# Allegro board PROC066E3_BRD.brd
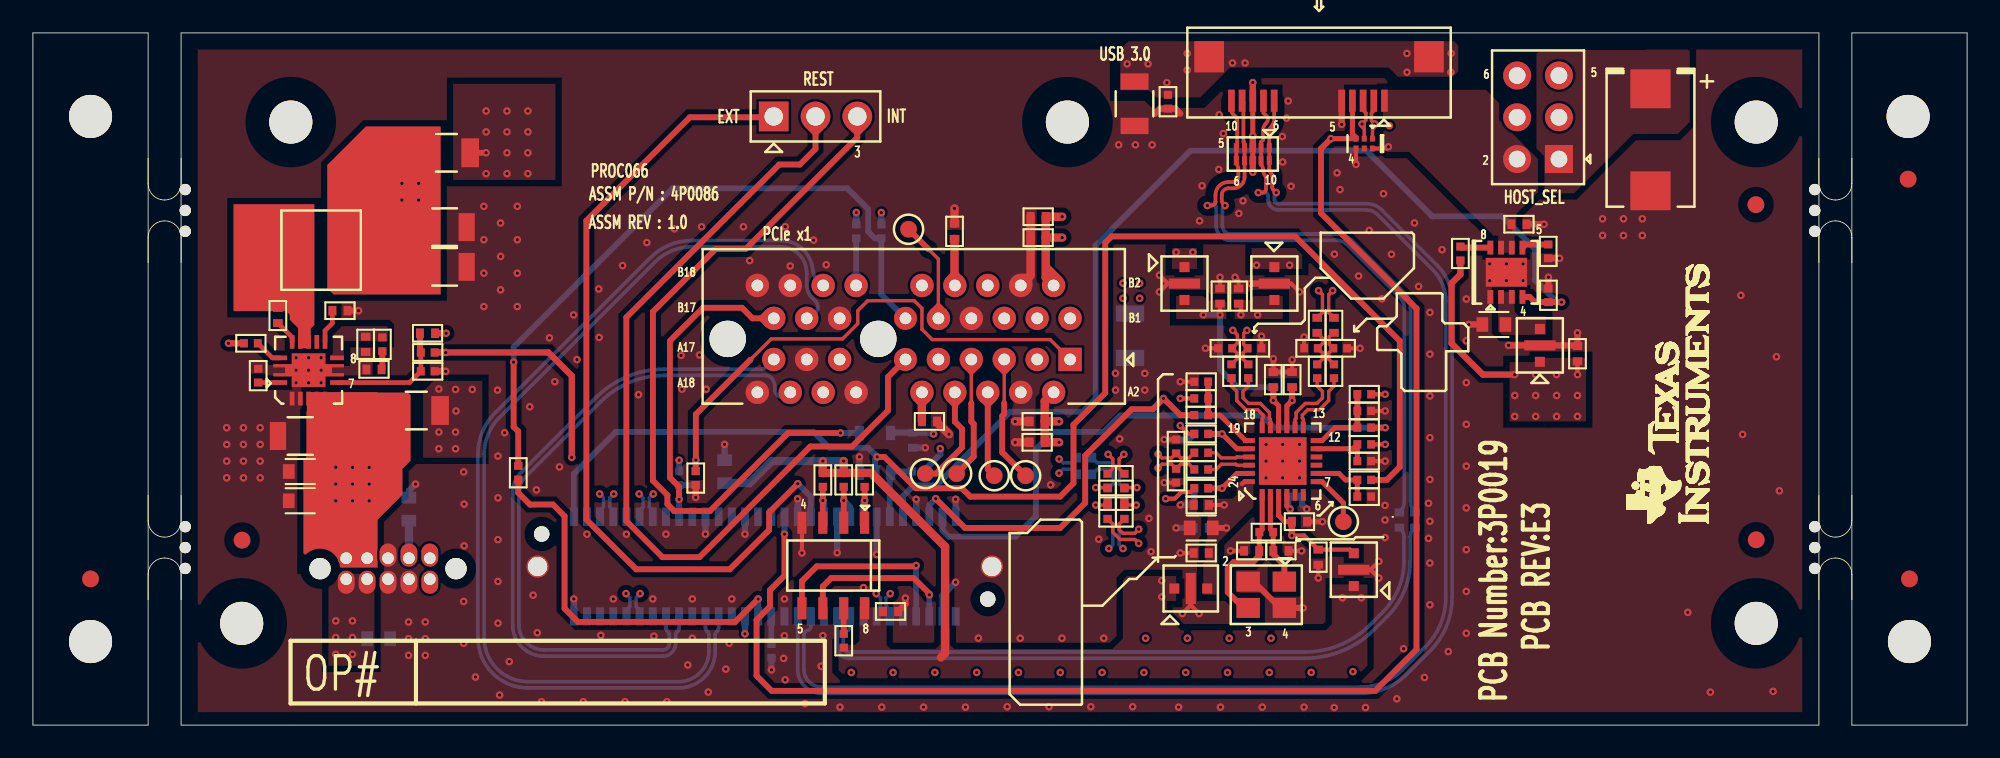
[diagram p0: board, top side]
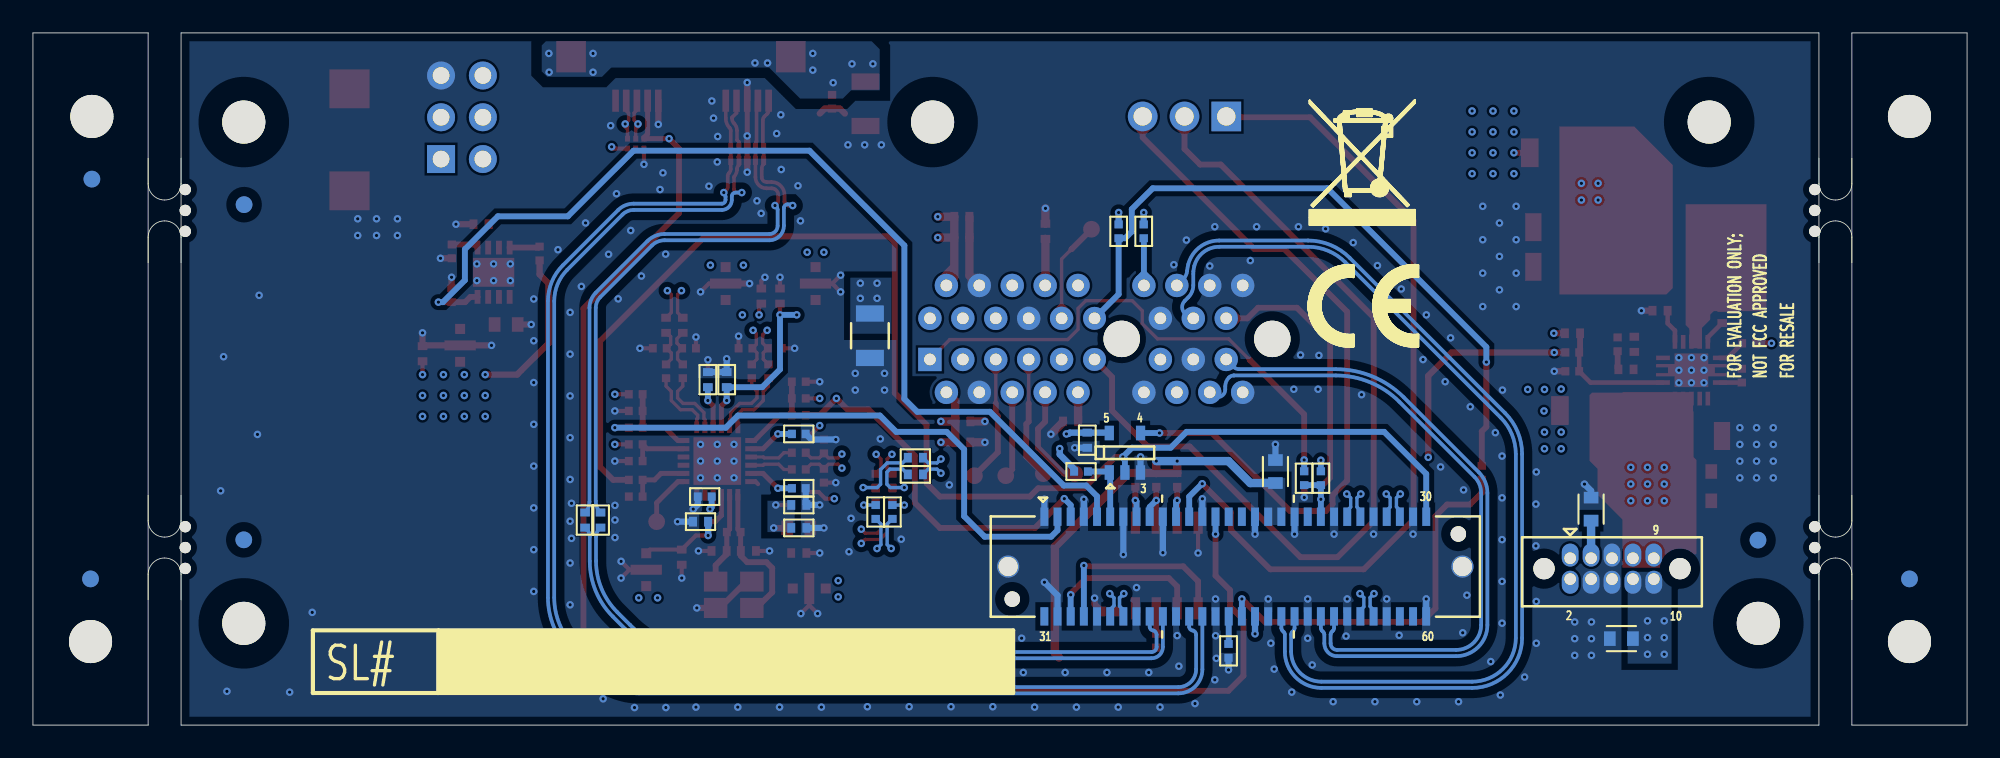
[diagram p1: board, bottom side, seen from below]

Outline 117.5 x 42.09 mm; copper layers: TOP, L02_GND1, L03_PWR, L04_SIG1, L05_GND2, BOTTOM. Coordinates in mm from the lower left corner of the outline.
Outline path: 0,42.09 0,0 7,0 7,42.09 0,42.09 ; 9,42.09 9,0 108.5,0 108.5,42.09 9,42.09 ; 110.5,42.09 110.5,0 117.5,0 117.5,42.09 110.5,42.09

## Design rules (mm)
net group 2_REFCLK_OUT1N: nets 2_REFCLK_OUT1N N17071009
net group 2_REFCLK_OUT1P: nets 2_REFCLK_OUT1P N17070998
net group DIFF_2_CLKGEN_REFCLK1: nets 2_CLKGEN_REFCLK1N 2_CLKGEN_REFCLK1P
net group DIFF_2_CLKGEN_REFCLK2: nets 2_CLKGEN_REFCLK2N 2_CLKGEN_REFCLK2P
net group DIFF_2_PCIE_REFCLK: nets 2_PCIE_REFCLK_N 2_PCIE_REFCLK_P
net group DIFF_2_REFCLK_IN1: nets 2_REFCLK_IN1N 2_REFCLK_IN1P
net group DIFF_2_REFCLK_OUT0: nets 2_REFCLK_OUT0N 2_REFCLK_OUT0P
net group DIFF_2_USB_D: nets 2_USB_DM 2_USB_DP
net group DIFF_CDCI2_Y1: nets CDCI2_Y1N CDCI2_Y1P
net group DIFF_CDCI2_Y2: nets CDCI2_Y2N CDCI2_Y2P
net group DIFF_CDCI2_Y3: nets CDCI2_Y3N CDCI2_Y3P
net group DIFF_CDCI2_Y3_R: nets N16935843 N16935846
net group 2_USB3_RXN: nets 2_USB3_RXN
net group 2_USB3_RXP: nets 2_USB3_RXP

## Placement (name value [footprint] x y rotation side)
C50  1000pF  [CAP1206]  66.92 37.78 270 top
C51  150uF_10V  [CAPT7343D_3-25]  98.27 35.59 270 top
C52  0.1uF  [CAP0402_0-75]  90.28 30.45 0 top
C53  0.01uF  [CAP0402]  61.07 30.91 180 top
C54  47uF  [CAP1206_2]  25 30.28 0 top
C55  0.1uF  [CAP0402_0-75]  55.99 30.02 90 top
C56  0.1uF  [CAP0402_0-75]  61.07 29.64 180 top
C57  10uF  [CAP0603_1]  88.76 24.36 180 top
C58  47uF  [CAP1206_2]  25 27.86 0 top
C59  0.1uF  [CAP0402_0-75]  93.84 22.58 90 top
C60  4.7uF  [CAP0402_0-75]  72.12 26.09 90 top
C61  4.7uF  [CAP0402_0-75]  73.25 26.09 90 top
C62  0.01uF  [CAP0402]  18.65 25.2 0 top
C63  0.1uF  [CAP0402_0-75]  14.88 24.9 270 top
C64  0.1uF  [CAP0402_0-75]  78.02 24.31 270 top
C65  0.1uF  [CAP0402_0-75]  79.04 24.31 270 top
C66  510pF  [CAP0402]  23.97 23.83 180 top
C67  91pF  [CAP0402]  20.21 23.15 270 top
C68  1500pF  [CAP0402]  20.72 21.63 180 top
C69  0.1uF  [CAP0402_0-75]  75.36 21.01 270 top
C70  0.1uF  [CAP0402_0-75]  76.5 21.01 270 top
C71  0.01uF  [CAP0402]  54.47 18.47 0 top
C72  0.1uF  [CAP0402_0-75]  61.01 18.47 180 top
C73  4.7uF  [CAP1206]  16.24 17.58 180 top
C74  0.01uF  [CAP0402]  61.01 17.2 180 top
C75  10uF  [CAP0603_1]  16.24 15.42 180 top
C76  10uF  [CAP0603_1]  16.24 13.64 180 top
C77  0.1uF  [CAP0402_0-75]  70.98 13.39 0 top
C78  0.1uF  [CAP0402_0-75]  76.94 12.37 180 top
C79  10uF  [CAP0603_1]  70.98 11.99 180 top
C80  27pF  [CAP0402]  74.04 10.59 0 top
C81  27pF  [CAP0402]  75.82 10.59 180 top
C82  4.7uF  [CAP0402_0-75]  70.98 10.46 180 top
C83  0.47uF  [CAP0402_0-75]  78.09 10.21 270 top
C84  0.1uF  [CAP0402_0-75]  52.1 6.91 0 top
C197  47uF  [CAP1206_2]  66.66 23.67 270 bottom
C198  0.47uF  [CAP0402_0-75]  76.5 21.01 90 bottom
C199  0.47uF  [CAP0402_0-75]  75.36 21.01 90 bottom
C200  0.1uF  [CAP0402_0-75]  53.45 17.32 270 bottom
C201  0.1uF  [CAP0402_0-75]  63.89 16.26 180 bottom
C202  10uF  [CAP0603_1]  42.02 15.42 90 bottom
C203  0.1uF  [CAP0402_0-75]  63.89 15.24 180 bottom
C204  0.47uF  [CAP0402_0-75]  70.98 13.39 180 bottom
C205  10uF  [CAP0603_1]  22.84 13.13 90 bottom
C206  4.7uF  [CAP0402_0-75]  76.94 12.37 0 bottom
C207  1uF  [CAP0402]  70.98 11.99 0 bottom
C208  10uF  [CAP0603_1]  21 5.26 0 bottom
C232  0.1uF  [CAP0402_0-75]  83.96 12.47 90 bottom
C233  0.1uF  [CAP0402_0-75]  83.02 12.47 90 bottom
FL6  4.7uF  [EMIFIL_NFM21P_0805_1]  91.55 23.09 90 top
FL7  0.47uF  [EMIFIL_NFM21P_0805]  69.96 26.85 270 top
FL8  0.47uF  [EMIFIL_NFM21P_0805]  75.42 26.85 270 top
FL9  0.47uF  [EMIFIL_NFM21P_0805]  80.25 9.45 90 top
FL10  0.47uF  [EMIFIL_NFM21P_0805]  70.34 8.31 0 top
J4  CON_MUSB-AB_10_F  [CON_USBAB10_UJ3-MIABH_S_R_S_2-8]  78.14 40.12 180 top
J5  HDR_2X3  [HDR_2X3_TSW-103-07-D_S_T_8-4]  92.71 34.42 90 top
J6  HDR_1X3  [HDR_3X1_100_S_T]  45 37.01 180 top
J7  CON_MINIPCI_2X18  [CON_MINIPCI36_10018784-10_S_S_T_11-3]  63.01 22.23 180 top
J18  CON_BTOB_2X30_171450_F  [CON_BTOB2X30_171450_S_S_S_4-6]  44.46 9.64 180 bottom
J19  RECP_2X5  [RECPT_2X5_SFC-105-T1-D-A_S_T_4-6]  24.11 10.15 180 bottom
L1  1uH  [IND_XFL4020_170X170_SMD_2-1]  17.51 28.88 0 top
NOREF  -  []  117.5 0 90 top
NOREF#2  -  []  0 0 0 top
NOREF#3  -  [unnamed#2]  8 10.79 270 top
NOREF#4  -  [unnamed#3]  3.5 37.01 0 top
NOREF#5  -  [unnamed#3]  114 5.08 0 top
NOREF#6  -  [unnamed#3]  12.7 11.25 0 top
NOREF#7  -  []  7 42.09 0 top
NOREF#8  -  [unnamed#3]  62.85 36.67 0 top
NOREF#9  -  []  94.59 8.92 0 top
NOREF#10  -  []  -49.27 -82.87 0 top
NOREF#11  -  []  15.65 5.13 0 top
NOREF#12  -  [unnamed#3]  114 8.89 0 top
NOREF#13  -  [unnamed#2]  8 31.29 270 top
NOREF#14  -  [unnamed#3]  104.69 11.27 0 top
NOREF#15  -  [unnamed#3]  3.5 8.89 0 top
NOREF#16  -  [unnamed#2]  109.5 10.79 90 top
NOREF#17  -  [unnamed#3]  104.68 31.64 0 top
NOREF#18  -  []  92.43 6.27 0 top
NOREF#19  -  [unnamed#3]  15.67 36.67 0 top
NOREF#20  -  [unnamed#2]  109.5 31.29 90 top
NOREF#21  -  []  -5.28 -40.82 0 top
NOREF#22  -  [unnamed#3]  113.92 37.01 0 top
NOREF#23  -  [unnamed#3]  113.92 33.2 0 top
NOREF#24  -  [unnamed#3]  104.69 6.19 0 top
NOREF#25  -  []  -49.37 -39.2 0 top
NOREF#26  -  [unnamed#3]  3.5 5.08 0 top
NOREF#27  -  [unnamed#3]  104.69 36.67 0 top
NOREF#28  -  []  0 42.09 0 top
NOREF#29  -  []  110.5 42.09 0 top
NOREF#30  -  [unnamed#3]  12.68 6.19 0 top
NOREF#31  -  []  -300 -133.86 0 top
NOREF#32  -  [unnamed#3]  114 8.89 180 bottom
NOREF#33  -  [unnamed#3]  113.92 33.2 180 bottom
NOREF#34  -  [unnamed#3]  104.68 31.64 180 bottom
NOREF#35  -  []  100.5 5.76 180 bottom
NOREF#36  -  []  37.49 25.5 180 bottom
NOREF#37  -  [unnamed#3]  104.69 11.27 180 bottom
NOREF#38  -  [unnamed#3]  12.7 11.25 180 bottom
NOREF#39  -  [unnamed#3]  3.5 8.89 180 bottom
R97  1M_1%  [RES0402]  68.96 37.9 270 top
R99  0E_1%  [RES1206]  25.12 34.8 0 top
R100  33.2K_1%  [RES0402]  92.06 28.8 270 top
R101  100K  [RES0402_0-5]  86.72 28.68 90 top
R102  10K_1%  [RES0402_0-5]  92.07 26.14 90 top
R103  100K  [RES0402_0-5]  13.24 23.22 0 top
R104  1.96K_1%  [RES0402]  21.23 23.15 270 top
R105  49.9E_1%  [RES0402_0-5]  72.44 22.91 180 top
R106  49.9E_1%  [RES0402_0-5]  74.21 22.91 0 top
R107  49.9E_1%  [RES0402_0-5]  77.64 22.91 180 top
R108  49.9E_1%  [RES0402_0-5]  79.42 22.91 0 top
R109  10K_1%  [RES0402_0-5]  23.99 22.66 0 top
R110  2.2K  [RES0402_0-5]  23.99 21.51 0 top
R111  33E_1%  [RES0402_0-5]  72.82 21.51 90 top
R112  33E_1%  [RES0402_0-5]  73.83 21.51 90 top
R113  33E_1%  [RES0402_0-5]  78.02 21.51 90 top
R114  33E_1%  [RES0402_0-5]  79.04 21.51 90 top
R115  34K_1%  [RES0402]  13.69 21.25 90 top
R116  4.7K  [RES0402]  70.98 20.88 180 top
R117  4.7K  [RES0402]  80.88 20.12 180 top
R118  4.7K  [RES0402]  70.98 19.86 0 top
R119  0E_1%  [RES1206]  23.29 19.13 0 top
R120  4.7K  [RES0402]  80.88 19.1 0 top
R121  0E  [RES0402_0-5]  70.98 18.85 0 top
R122  0E  [RES0402_0-5]  80.88 18.08 180 top
R123  4.7K  [RES0402]  70.98 17.7 0 top
R124  4.7K  [RES0402]  80.88 17.07 180 top
R125  49.9E_1%  [RES0402_0-5]  69.45 16.94 90 top
R126  33E_1%  [RES0402_0-5]  70.98 16.56 180 top
R127  4.7K  [RES0402]  80.88 16.05 0 top
R128  33E_1%  [RES0402_0-5]  70.98 15.54 180 top
R129  49.9E_1%  [RES0402_0-5]  69.45 15.16 270 top
R130  0E  [RES0402_0-5]  40.27 15.02 90 top
R131  10K_1%  [RES0402_0-5]  47.99 14.91 270 top
R132  10K_1%  [RES0402_0-5]  49.26 14.91 270 top
R133  10K_1%  [RES0402_0-5]  50.53 14.91 270 top
R134  0E  [RES0402_0-5]  80.88 14.91 180 top
R135  0E  [RES0402_0-5]  65.29 14.86 90 top
R136  0E  [RES0402_0-5]  66.31 14.86 90 top
R138  1K  [RES0402_0-5]  70.98 14.4 0 top
R139  0E  [RES0402_0-5]  65.29 13.97 270 top
R140  0E  [RES0402_0-5]  66.31 13.97 270 top
R141  4.7K  [RES0402]  80.88 13.89 0 top
R142  0E  [RES0402_0-5]  65.29 12.96 270 top
R143  0E  [RES0402_0-5]  66.31 12.96 270 top
R144  1M_1%  [RES0402]  74.93 11.73 0 top
R145  10K_1%  [RES0402_0-5]  49.26 5.13 90 top
R272  10K_1%  [RES0402_0-5]  51.54 30.02 270 bottom
R273  10K_1%  [RES0402_0-5]  50.02 30.02 270 bottom
R274  4.7K  [RES0402]  70.98 17.7 180 bottom
R275  10K_1%  [RES0402_0-5]  53.83 15.42 0 bottom
R276  0E  [RES0402_0-5]  40.27 15.01 90 bottom
R277  10K_1%  [RES0402_0-5]  39.26 15.01 270 bottom
R278  1K  [RES0402_0-5]  70.98 14.4 180 bottom
R279  4.7K  [RES0402]  76.69 13.89 0 bottom
R280  0E  [RES0402_0-5]  66.31 12.96 270 bottom
R281  0E  [RES0402_0-5]  65.29 12.96 270 bottom
R282  0E  [RES0402_0-5]  44.87 4.51 270 bottom
R309  0E  [RES0402_0-5]  29.49 15.34 90 top
TP5  SMD  [TP40_SMD]  53.2 30.15 0 top
TP6  SMD  [TP40_SMD]  54.21 15.29 0 top
TP7  SMD  [TP40_SMD]  56.12 15.29 0 top
TP8  SMD  [TP40_SMD]  58.4 15.16 0 top
TP9  SMD  [TP40_SMD]  60.31 15.16 0 top
TP10  SMD  [TP40_SMD]  79.61 12.37 270 top
U8  TPD4S012DRYR  [SON6_19-68_40X60_PB_0-6]  80.88 35.36 270 top
U9  TPD4E02B04DQAR  [USON10_19-68_40X100_0-6]  74.11 34.72 270 top
U10  TPS2557  [SON8_25-59_130X130_1]  89.52 27.53 90 top
U11  TPS54821RHLT  [QFN14_19-68_145X145]  16.75 21.58 0 top
U12  CDCI6214RGET  [QFN24_19-68_160X160_1]  75.93 16.05 90 top
U13  CAT24C256WI-GT3  [SOIC8_1-8]  48.62 9.7 270 top
U26  SN74LVC1G08DBVRE4  [SOT23-5]  51.16 16.56 90 bottom
Y4  25.000MHz  [XTAL4_NX3225GA_130X100_SMD]  74.93 7.92 180 top

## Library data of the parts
C50 C52-C84 C197-C200 C202 C204-C208 = CAP
C51 = CAP_POL
C201 C203 = CAP: signal model: cap
C232 C233 = CAP: signal model: CAP_CAP0402_0-75_0.1UF_0.1uF
FL6 = EMI_FILTER
FL7-FL10 = CAP_FILTER
J4 = CON_MUSB-AB_10_UJ3-MIABH
J5 = HEADER_3X2
J6 = HEADER_3X1
J7 = CON_MINIPCI_18X2
J18 = CON_BTOB_30X2_171450
J19 = RECP_5X2
L1 = INDUCTOR
R97 R99-R136 R138-R145 R272-R282 R309 = RESISTOR
TP5-TP10 = TESTPOINT
U8 = TPD4S012DRY_SON6
U9 = TPD4E02B04DQAR_USON10
U10 = TPS2556DRBT_SON8
U11 = TPS54620_QFN14
U12 = CDCI6214RGET_VQFN24
U13 = CAT24C256WI-GT3_SOIC8
U26 = SN74LVC1G08DBVRE4_SOT23-5
Y4 = CRY_CX3225GB

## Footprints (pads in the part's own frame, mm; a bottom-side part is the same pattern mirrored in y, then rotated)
CAP0402
  rect 0.483x0.584 smd: 1(-0.46,0) 2(0.46,0)
CAP0402_0-75
  rect 0.483x0.584 smd: 1(-0.46,0) 2(0.46,0)
CAP0603_1
  rect 0.711x0.889 smd: 1(-0.7,0) 2(0.7,0)
CAP1206
  rect 0.991x1.702 smd: 1(-1.35,0) 2(1.35,0)
CAP1206_2
  rect 0.991x1.702 smd: 1(-1.35,0) 2(1.35,0)
CAPT7343D_3-25
  rect 2.362x2.438 smd: 1(-3.1,0) 2(3.1,0)
CON_BTOB2X30_171450_S_S_S_4-6
  round 0.94 hole 1.067 unplated: (-13.55,-1.98) (13.55,1.98)
  rect 0.483x1.118 smd: 1(-11.6,3.03) 2(-10.8,3.03) 3(-10,3.03) 4(-9.2,3.03) 5(-8.4,3.03) 6(-7.6,3.03) 7(-6.8,3.03) 8(-6,3.03) 9(-5.2,3.03) 10(-4.4,3.03) 11(-3.6,3.03) 12(-2.8,3.03) 13(-2,3.03) 14(-1.2,3.03) 15(-0.4,3.03) 16(0.4,3.03) 17(1.2,3.03) 18(2,3.03) 19(2.8,3.03) 20(3.6,3.03) 21(4.4,3.03) 22(5.2,3.03) 23(6,3.03) 24(6.8,3.03) 25(7.6,3.03) 26(8.4,3.03) 27(9.2,3.03) 28(10,3.03) 29(10.8,3.03) 30(11.6,3.03) 31(-11.6,-3.03) 32(-10.8,-3.03) 33(-10,-3.03) 34(-9.2,-3.03) 35(-8.4,-3.03) 36(-7.6,-3.03) 37(-6.8,-3.03) 38(-6,-3.03) 39(-5.2,-3.03) 40(-4.4,-3.03) 41(-3.6,-3.03) 42(-2.8,-3.03) 43(-2,-3.03) 44(-1.2,-3.03) 45(-0.4,-3.03) 46(0.4,-3.03) 47(1.2,-3.03) 48(2,-3.03) 49(2.8,-3.03) 50(3.6,-3.03) 51(4.4,-3.03) 52(5.2,-3.03) 53(6,-3.03) 54(6.8,-3.03) 55(7.6,-3.03) 56(8.4,-3.03) 57(9.2,-3.03) 58(10,-3.03) 59(10.8,-3.03) 60(11.6,-3.03)
  round 1.346 hole 1.168: SH1(-13.8,0) SH2(13.8,0)
CON_MINIPCI36_10018784-10_S_S_T_11-3
  round 2.21 hole 2.337 unplated: (11.65,-1.25) (20.8,-1.25)
  rect 1.422x1.422 hole 0.711: A1(0,0)
  round 1.422 hole 0.711: A2(1,2) A3(2,0) A4(3,2) A5(4,0) A6(5,2) A7(6,0) A8(7,2) A9(8,0) A10(9,2) A12(13,2) A13(14,0) A14(15,2) A15(16,0) A16(17,2) A17(18,0) A18(19,2) B1(0,-2.5) B2(1,-4.5) B3(2,-2.5) B4(3,-4.5) B5(4,-2.5) B6(5,-4.5) B7(6,-2.5) B8(7,-4.5) B9(8,-2.5) B10(9,-4.5) B12(13,-4.5) B13(14,-2.5) B14(15,-4.5) B15(16,-2.5) B16(17,-4.5) B17(18,-2.5) B18(19,-4.5)
  round 1.397 hole 0.711: A11(10,0) B11(10,-2.5)
CON_USBAB10_UJ3-MIABH_S_R_S_2-8
  rect 0.406x1.346 smd: 1(-3.975,2.158) 2(-3.325,2.158) 3(-2.675,2.158) 4(-2.025,2.158) 5(-1.375,2.158) 6(2.725,2.158) 7(3.375,2.158) 8(4.025,2.158) 9(4.675,2.158) 10(5.325,2.158)
  rect 1.803x1.905 smd: SH1(-6.675,-0.517) SH2(6.675,-0.517)
EMIFIL_NFM21P_0805
  rect 0.61x0.61 smd: 1(-1,0) 3(1,0)
  rect 0.61x1.905 smd: 2(0,0)
EMIFIL_NFM21P_0805_1
  rect 0.61x0.61 smd: 1(-1,0) 3(1,0)
  rect 0.61x1.905 smd: 2(0,0)
HDR_2X3_TSW-103-07-D_S_T_8-4
  rect 1.702x1.702 hole 1.016: 1(0,0)
  round 1.702 hole 1.016: 2(0,2.54) 3(2.54,0) 4(2.54,2.54) 5(5.08,0) 6(5.08,2.54)
HDR_3X1_100_S_T
  rect 1.803x1.803 hole 1.118: 1(0,0)
  round 1.803 hole 1.118: 2(-2.54,0) 3(-5.08,0)
IND_XFL4020_170X170_SMD_2-1
  rect 1.448x3.708 smd: 1(-1.225,0) 2(1.225,0)
QFN14_19-68_145X145
  rect 0.838x0.279 smd: 1(-1.725,-0.75) 7(1.725,-0.75) 8(1.725,0.75) 14(-1.725,0.75)
  rect 0.279x0.838 smd: 2(-1,-1.725) 3(-0.5,-1.725) 4(0,-1.725) 5(0.5,-1.725) 6(1,-1.725) 9(1,1.725) 10(0.5,1.725) 11(0,1.725) 12(-0.5,1.725) 13(-1,1.725)
  custom 0.512x0.512 smd: 15(0,0)
QFN24_19-68_160X160_1
  rect 0.711x0.305 smd: 1(-2.05,1.25) 2(-2.05,0.75) 3(-2.05,0.25) 4(-2.05,-0.25) 5(-2.05,-0.75) 6(-2.05,-1.25) 13(2.05,-1.25) 14(2.05,-0.75) 15(2.05,-0.25) 16(2.05,0.25) 17(2.05,0.75) 18(2.05,1.25)
  rect 0.305x0.711 smd: 7(-1.25,-2.05) 8(-0.75,-2.05) 9(-0.25,-2.05) 10(0.25,-2.05) 11(0.75,-2.05) 12(1.25,-2.05) 19(1.25,2.05) 20(0.75,2.05) 21(0.25,2.05) 22(-0.25,2.05) 23(-0.75,2.05) 24(-1.25,2.05)
  rect 2.896x2.896 smd: 25(0,0)
RECPT_2X5_SFC-105-T1-D-A_S_T_4-6
  round 1.295 hole 1.422 unplated: (-1.59,-0.635) (6.67,-0.635)
  oval 1.016x1.397 hole 0.711: 1(0,0) 2(0,-1.27) 3(1.27,0) 4(1.27,-1.27) 5(2.54,0) 6(2.54,-1.27) 7(3.81,0) 8(3.81,-1.27) 9(5.08,0) 10(5.08,-1.27)
RES0402
  rect 0.483x0.508 smd: 1(-0.42,0) 2(0.42,0)
RES0402_0-5
  rect 0.483x0.508 smd: 1(-0.42,0) 2(0.42,0)
RES1206
  rect 1.067x1.753 smd: 1(-1.45,0) 2(1.45,0)
SOIC8_1-8
  rect 1.346x0.559 smd: 1(-2.6,1.905) 2(-2.6,0.635) 3(-2.6,-0.635) 4(-2.6,-1.905) 5(2.6,-1.905) 6(2.6,-0.635) 7(2.6,0.635) 8(2.6,1.905)
SON6_19-68_40X60_PB_0-6
  rect 0.356x0.305 smd: 1(-0.3,0.5) 2(-0.3,0) 3(-0.3,-0.5) 4(0.3,-0.5) 5(0.3,0) 6(0.3,0.5)
SON8_25-59_130X130_1
  rect 0.838x0.356 smd: 1(-1.5,0.975) 2(-1.5,0.325) 3(-1.5,-0.325) 4(-1.5,-0.975) 5(1.5,-0.975) 6(1.5,-0.325) 7(1.5,0.325) 8(1.5,0.975)
  rect 1.753x2.515 smd: 9(0,0)
SOT23-5
  rect 0.889x0.559 smd: 1(-1.2,0.95) 2(-1.2,0) 3(-1.2,-0.95) 4(1.2,-0.95) 5(1.2,0.95)
TP40_SMD
  round 1.016 smd: 1(0,0)
unnamed#2
  round 0.686 hole 0.813 unplated: (-1.27,1.254) (0,1.254) (1.27,1.254)
unnamed#3
  round 2.616 hole 2.743 unplated: (0,0)
USON10_19-68_40X100_0-6
  rect 0.559x0.305 smd: 1(-0.385,1) 2(-0.385,0.5) 4(-0.385,-0.5) 5(-0.385,-1) 6(0.385,-1) 7(0.385,-0.5) 9(0.385,0.5) 10(0.385,1)
  rect 0.559x0.406 smd: 3(-0.385,0) 8(0.385,0)
XTAL4_NX3225GA_130X100_SMD
  rect 1.422x1.219 smd: 1(-1.1,-0.8) 2(1.1,-0.8) 3(1.1,0.8) 4(-1.1,0.8)

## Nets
DGND2: C50.2 C51.2 C52.2 C53.2 C54.2 C55.2 C56.2 C57.2 C58.2 C59.2 C60.2 C61.2 C62.2 C67.2 C68.2 C69.1 C70.1 C71.2 C72.2 C73.2 C74.2 C75.2 C76.2 C77.1 C78.1 C79.2 C80.1 C81.1 C82.2 C83.2 C84.2 C197.2 C198.2 C199.2 C200.2 C202.2 C204.2 C205.2 C206.2 C207.1 C208.2 FL6.2(GND) FL7.2(GND1) FL8.2(GND1) FL9.2(GND1) FL10.2(GND1) J4.5(GND#5) J4.8(GND#8) J5.5 J7.A4(GND#A4) J7.A12(GND#A12) J7.A15(GND#A15) J7.A18(GND#A18) J7.B4(GND#B4) J7.B7(GND#B7) J7.B13(GND#B13) J7.B16(GND#B16) J7.B18(GND#B18) J18.1 J18.4 J18.7 J18.10 J18.13 J18.17 J18.20 J18.23 J18.26 J18.29 J18.32 J18.35 J18.38 J18.41 J18.44 J18.48 J18.51 J18.54 J18.57 J18.60 J18.SH1 J18.SH2 J19.4 J19.5 J19.6 R97.2 R100.2 R102.2 R105.2 R106.2 R107.2 R108.2 R110.2 R115.2 R116.2 R120.2 R125.2 R127.2 R129.2 R130.1 R141.2 R274.2 R278.2 R279.2 R282.2 U8.4(GND) U9.3(GND#3) U9.8(GND#8) U10.1(GND) U10.9(EP) U11.2(GND1) U11.3(GND2) U11.15(PAD) U12.25(GND) U13.4(VSS) U26.3(GND) Y4.2(NC1) Y4.4(NC2)
V3V3_REF_CDCI2: C78.2 C83.1 C206.1 FL9.3(OUT) U12.3(VDDREF)
V3V3_VCO_CDCI2: C77.2 C79.1 C82.1 C204.1 C207.2 FL10.3(OUT) U12.24(VDDVCO)
VDD12_CDCI2: C60.1 C69.2 C199.1 FL7.3(OUT) U12.16(VDDO12)
VDD34_CDCI2: C61.1 C70.2 C198.1 FL8.3(OUT) U12.15(VDDO34)
2_BOARDID_A0: J18.8 R133.2 U13.1(A0)
2_BOARDID_A1: J18.9 R132.2 U13.2(A1)
2_BOARDID_A2: J18.11 R131.2 U13.3(A2)
2_BRD_DET: J18.45 R282.1
2_CLKGEN_REFCLK1N: R125.1 R126.2 R142.2
2_CLKGEN_REFCLK1P: R128.2 R129.1 R143.2
2_CLKGEN_REFCLK2N: R106.1 R112.2 R135.2
2_CLKGEN_REFCLK2P: R105.1 R111.2 R136.2
2_EEPROM_WP: R145.2 U13.7(WP)
2_MCU_SCL: J7.B5(SMCLK) J18.2 R122.1
2_MCU_SDA: J7.B6(SMDAT) J18.3 R121.1
2_PCIE_CLKREQN: J7.B12(RSVD_B12) R273.2
2_PCIE_PRSNT1N: J7.A1(PRSNT1#) R130.2 R276.2
2_PCIE_PRSNT2N: J7.B17(PRSNT2#) J18.22 R276.1 R277.2
2_PCIE_REFCLK_N: J7.A14(REFCLK-) R139.2 R142.1 R281.1
2_PCIE_REFCLK_P: J7.A13(REFCLK+) R140.2 R143.1 R280.1
2_PCIE_RESETN: J6.2 J7.A11(PERST#)
2_PCIE_RST: J18.6 R275.1 U26.1(A)
2_PCIE_RXN: J7.A17(PERN0) J18.52
2_PCIE_RXP: J7.A16(PERP0) J18.53
2_PCIE_TCK: J7.A5(CK_JTAG) TP9.1(TP)
2_PCIE_TDI: J7.A6(DI_JTAG) TP8.1(TP)
2_PCIE_TDO: J7.A7(DO_JTAG) TP7.1(TP)
2_PCIE_TMS: J7.A8(MS_JTAG) TP6.1(TP)
2_PCIE_TRSTN: J7.B9(RST_JTAG) TP5.1(TP)
2_PCIE_TXN: J7.B15(PETN0) J18.50
2_PCIE_TXP: J7.B14(PETP0) J18.49
2_PCIE_WAKEN: J7.B11(WAKE#) R272.2 R309.2
2_PCIE_WAKEN_3V3: J18.46 R309.1
2_PORZ: J6.1 J18.12
2_PORZ_OUT: J18.30 R134.1 U26.2(B)
2_REFCLK_IN1N: J18.27 R281.2
2_REFCLK_IN1P: J18.28 R280.2
2_REFCLK_OUT0N: C65.1 J18.24
2_REFCLK_OUT0P: C64.1 J18.25
2_REFCLK_OUT1N: C203.2 J18.55
2_REFCLK_OUT1P: C201.2 J18.56
2_RESETN: J6.3 U26.4(Y)
2_USB3_RXN: C232.1 J18.40
2_USB3_RXN_DB: C232.2 J4.9(RX-) U9.4(IO3) U9.7(NC2)
2_USB3_RXP: C233.1 J18.39
2_USB3_RXP_DB: C233.2 J4.10(RX+) U9.5(IO4) U9.6(NC1)
2_USB3_TXN: J4.6(TX-) J18.43 U9.1(IO1) U9.10(NC4)
2_USB3_TXP: J4.7(TX+) J18.42 U9.2(IO2) U9.9(NC3)
2_USB_DM: J4.2(D-) J18.36 U8.1(D+)
2_USB_DP: J4.3(D+) J18.37 U8.2(D-)
2_USB_DRV_VBUS: J18.5 R102.1 U10.4(EN)
2_USB_ID: J4.4(ID) J5.6 J18.14 U8.3(ID)
2_USB_VBUS: C52.1 J4.1(VBUS) J5.2 J18.47 U8.6(VBUS) U10.6(OUT1) U10.7(OUT2)
2_VCC_1V8: C205.1 FL7.1(IN) FL8.1(IN) J19.3
2_VCC_3V3: C54.1 C58.1 C66.1 C200.1 L1.2 R99.1 R103.1 R109.2 R275.2 U26.5(VCC)
2_VCC_5V: C59.1 C208.1 FL6.1(I) J19.8 J19.10 R101.1
2_VCC_12V: C73.1 C75.1 C76.1 J19.7 J19.9 R119.1 U11.4(PVIN1) U11.5(PVIN2) U11.6(VIN)
2_VCC_FUN_3V3: C84.1 C202.1 FL9.1(IN) FL10.1(IN) J18.18 J18.19 R117.1 R118.1 R123.1 R124.1 R131.1 R132.1 R133.1 R138.1 R145.1 U13.8(VCC)
2_VCC_PCIE_3V3: C55.1 C71.1 J7.A9(+3.3V#A9) J7.A10(+3.3V#A10) J7.B8(+3.3V#B8) J7.B10(3.3VAUX) R99.2 R272.1 R273.1 R277.1
2_VCC_PCIE_12V: C53.1 C56.1 C72.1 C74.1 C197.1 J7.A2(+12V#A2) J7.A3(+12V#A3) J7.B1(+12V#B1) J7.B2(+12V#B2) J7.B3(RSVD_B3) R119.2
2_WKUP_SCL: J18.33 U13.6(SCL)
2_WKUP_SDA: J18.34 U13.5(SDA)
CDCI2_EEPROMSEL: R138.2 R278.1 U12.23(EEPROMSEL)
CDCI2_OE1: R123.2 R274.1 U12.20(STATUS/GPIO1)
CDCI2_OE2: R116.1 R118.2 R121.2 U12.19(SDA/GPIO2)
CDCI2_OE3: R117.2 R120.1 R122.2 U12.12(SCL/GPIO3)
CDCI2_OE4: R124.2 R127.1 U12.11(OE/GPIO4)
CDCI2_REFSEL: R279.1 U12.4(REFSEL)
CDCI2_RST: R134.2 R141.1 U12.8(RESETN/SYNC)
CDCI2_XIN: C80.2 R144.1 U12.1(XIN) Y4.3(HOT2)
CDCI2_XOUT: C81.2 R144.2 U12.2(XOUT) Y4.1(HOT1)
CDCI2_Y0: TP10.1(TP) U12.7(Y0)
CDCI2_Y1N: R126.1 U12.21(Y1N)
CDCI2_Y1P: R128.1 U12.22(Y1P)
CDCI2_Y2N: R112.1 U12.17(Y2N)
CDCI2_Y2P: R111.1 U12.18(Y2P)
CDCI2_Y3N: R114.1 U12.13(Y3N)
CDCI2_Y3P: R113.1 U12.14(Y3P)
FAULTN: R101.2 U10.8(F\A\U\L\T\)
PWR_GOOD2: R103.2 U11.14(PWRGD)
USB_SHIELD2: C50.1 J4.SH1 J4.SH2 R97.1
N16935843: C65.2 R108.1 R114.2
N16935846: C64.2 R107.1 R113.2
N17014016: C66.2 R109.1 R110.1 U11.7(VSENSE)
N17014112: C63.1 L1.1 U11.11(PH1) U11.12(PH2)
N17014164: C68.1 R104.2
N17014166: C67.1 R104.1 U11.8(COMP)
N17014176: R115.1 U11.1(RT/CLK)
N17014182: C62.1 U11.9(SS/TR)
N17014200: C63.2 U11.13(BOOT)
N17025145: C57.1 FL6.3(O) U10.2(IN1) U10.3(IN2)
N17027241: R100.1 U10.5(ILIM)
N17070998: C201.1 R136.1 R140.1
N17071009: C203.1 R135.1 R139.1
N17801417: C51.1 J5.1

Pads without a net: J5 3 4; J18 15 16 21 31 58 59; J19 1 2; U8 5; U11 10; U12 5 6 9 10

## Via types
v1: diameter 0.457, hole 0.203, TOP to BOTTOM, 452 vias

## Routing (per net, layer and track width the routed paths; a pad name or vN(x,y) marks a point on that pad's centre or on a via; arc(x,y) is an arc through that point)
DGND2: length 87.2
  TOP w0.254: R106.2 v1(74.63,23.65) ; v1(75.36,22.28) C69.1 C70.1 v1(76.5,22.21) ; R105.2 v1(71.23,22.91) ; C83.2 v1(78.09,8.94) ; R120.2 v1(82.15,19.1) ; v1(69.83,6.78) 70.34,7.29 ; 70.34,7.29 FL10.2 ; 70.34,7.29 v1(70.85,6.78) ; v1(68.44,26.34) 68.94,26.85 ; 68.94,26.85 FL7.2 ; 68.94,26.85 v1(68.44,27.36) ; R107.2 v1(77.22,23.6) ; R116.2 v1(69.71,20.88) ; v1(81.77,9.96) 81.26,9.45 ; 81.26,9.45 v1(81.77,8.94) ; 81.26,9.45 FL9.2 ; R108.2 v1(80.63,22.91) ; FL8.2 76.44,26.85 v1(76.94,26.34) ; v1(73.03,27.23) 73.25,27.01 C61.2 ; U13.4 v1(46.72,10.46) ; R127.2 v1(82.15,16.05) ; C78.1 v1(78.34,12.37) ; R125.2 v1(68.73,17.36) ; C80.1 v1(72.75,10.59) ; U8.4 v1(80.38,34.09) ; R129.2 v1(68.73,14.74) ; C81.1 v1(77.07,10.59) ; C82.2 v1(69.71,10.46) ; C60.2 v1(72.12,27.23)
  TOP w0.305: U9.8 U9.3 ; v1(74.11,35.82) J4.8
  TOP w0.356: Y4.4 75.77,7.12 74.17,8.72 Y4.2
  TOP w0.381: v1(53.01,7.72) 53.01,7.35 C84.2 ; v1(89.64,23.09) FL6.2 93.79,23.09 C59.2 v1(93.84,23.85) ; R100.2 v1(92.74,28.38) ; R102.2 v1(92.07,27.23) ; U9.8 v1(74.11,33.62) ; R110.2 v1(25.08,21.51) ; 68.18,37.18 68.48,37.48 R97.2 69.4,37.48 69.7,37.18 ; J4.5 v1(79.51,36.53) ; v1(73.97,26.85) FL8.2 ; U9.3 v1(74.11,35.82) ; Y4.4 v1(77.17,7.12) ; J4.8 v1(74.11,39.07) ; C62.2 v1(19.79,25.2) ; C52.2 v1(91.8,30.45) ; C57.2 v1(87.23,24.36) ; R130.1 v1(40.27,13.84)
  TOP w0.508: v1(55.66,17.69) 54.93,18.42 C71.2 ; C74.2 v1(59.67,17.2) ; C72.2 v1(59.67,18.47) ; J7.B4 60.61,27.33 C56.2 C53.2 ; C55.2 v1(55.99,31.42)
  BOTTOM w0.381: C70.1 C69.1 v1(75.36,22.28) ; J18.20 v1(40.86,11.61) ; C202.2 v1(42.02,17.07) ; C200.2 v1(54.21,16.86) ; R274.2 70.21,17.36 v1(68.73,17.36) ; C207.1 v1(69.45,11.99) ; v1(69.71,13.39) C77.1 70.56,13.43 R278.2 ; J18.32 55.26,7.89 v1(56.05,8.69) ; J18.7 v1(51.26,10.37) ; J18.13 v1(46.46,13.76) ; C205.2 22.84,14.25 v1(23.24,14.65) ; J18.60 v1(32.86,7.67) ; R282.2 v1(44.87,3.36) ; J18.17 v1(43.26,11.61) ; J18.10 v1(48.86,10.48) ; J18.1 v1(56.06,13.73) ; v1(77.39,13.13) 77.11,13.41 R279.2 ; J18.4 v1(53.66,13.73) ; U26.3 v1(50.21,16.31) ; C78.1 v1(78.34,12.37)
  vias: v1(11.77,18.08) v1(11.77,17.07) v1(11.77,16.05) v1(11.77,15.03) v1(12.79,18.08) v1(12.79,17.07) v1(12.79,16.05) v1(12.79,15.03) v1(13.81,18.08) v1(13.81,17.07) v1(13.81,16.05) v1(13.81,15.03) v1(15.98,22.34) v1(15.98,21.58) v1(15.98,20.82) v1(16.75,22.34) v1(16.75,21.58) v1(16.75,20.82) v1(17.51,22.34) v1(17.51,21.58) v1(17.51,20.82) v1(22.82,6.27) v1(22.82,5.26) v1(22.82,4.24) v1(23.84,6.27) v1(23.84,5.26) v1(23.84,4.24) v1(26.17,15.39) v1(26.2,13.44) v1(26.2,10.9) v1(26.17,7.52) v1(26.17,4.98) v1(26.88,2.92) v1(27.39,31.54) v1(27.39,29.51) v1(27.39,27.48) v1(27.39,25.45) v1(28.23,20.37) v1(28.25,16.36) v1(28.25,13.82) v1(28.25,11.28) v1(28.25,8.74) v1(28.25,6.2) v1(28.41,30.53) v1(28.41,28.5) v1(28.41,26.46) v1(28.35,1.83) v1(28.66,17.78) v1(28.94,3.86) v1(29.43,31.54) v1(29.43,29.51) v1(29.43,27.48) v1(29.43,25.45) v1(30.18,19.35) v1(30.39,7.9) v1(30.59,14.3) v1(30.64,5.61) v1(30.89,1.42) v1(31.38,23.55) v1(31.71,20.88) v1(31.99,15.7) v1(32.85,24.94) v1(33.05,22.23) v1(33.43,1.42) v1(33.66,11.61) v1(34.37,26.52) v1(34.4,23.57) v1(34.5,5.46) v1(35.26,7.67) v1(35.82,27.94) v1(35.97,1.42) v1(36.06,11.61) v1(36.79,20.09) v1(37.3,29.34) v1(37.66,7.67) v1(37.73,5.41) v1(38.46,11.61) v1(38.51,1.42) v1(38.97,30.18) v1(39.38,22.48) v1(39.43,20.42) v1(39.78,3.66) v1(40.06,7.67) v1(40.06,5.28) v1(40.5,22.5) v1(40.62,30.3) v1(40.9,20.42) v1(41.03,2.01) v1(42.1,3.4) v1(42.3,4.98) v1(42.46,7.67) v1(43.16,30.3) v1(43.54,28.24) v1(45.61,4.06) v1(45.7,30.3) v1(45.66,7.67) v1(45.65,5.44) v1(45.7,2.75) v1(46.01,27.91) v1(46.91,1.31) v1(47.43,29.49) v1(47.89,3.58) v1(47.99,5.44) v1(48.19,27.99) v1(49.03,1.09) v1(49.72,3.2) v1(50.46,8.36) v1(51.57,1.09) v1(52.26,3.2) v1(54.11,1.09) v1(54.8,3.2) v1(56.65,1.09) v1(57.34,3.2) v1(57.44,5.28) v1(59.19,1.12) v1(59.88,3.2) v1(59.98,5.28) v1(61.73,1.12) v1(61.83,14.61) v1(62.42,3.2) v1(62.52,5.28) v1(64.27,1.12) v1(64.75,11.3) v1(64.96,3.2) v1(65.06,5.28) v1(65.77,21.39) v1(65.77,20.37) v1(65.96,35.28) v1(66.02,17.4) v1(66.81,1.12) v1(66.98,35.28) v1(67.55,21.39) v1(67.55,20.37) v1(67.5,3.2) v1(67.6,5.28) v1(67.8,12.57) v1(67.93,10.54) v1(67.99,35.28) v1(69.6,1.09) v1(70.04,3.2) v1(70.14,5.28) v1(70.87,30.66) v1(71.03,32.79) v1(72.04,33.78) v1(72.07,37.11) v1(72.14,1.09) v1(72.32,35.97) v1(72.58,3.2) v1(72.68,5.28) v1(73.26,31.11) v1(73.52,31.88) v1(74.68,1.09) v1(74.91,17.07) v1(74.91,16.05) v1(74.91,15.04) v1(75.12,3.2) v1(75.22,5.28) v1(75.9,35.79) v1(75.93,34.24) v1(75.93,17.07) v1(75.93,16.05) v1(75.93,15.04) v1(76.16,36.91) v1(76.26,37.95) v1(76.44,32.77) v1(76.94,17.07) v1(76.94,16.05) v1(76.94,15.04) v1(77.22,1.09) v1(77.66,3.2) v1(79.07,28.64) v1(79.05,1.07) v1(79.23,33.58) v1(79.41,32.56) v1(80.2,3.25) v1(80.54,27.3) v1(80.96,1.07) v1(81.19,30.07) v1(81.95,25.92) v1(82.05,32.31) v1(82.14,13.36) v1(82.14,12.47) v1(82.14,11.4) v1(82.41,36.45) v1(82.53,28.63) v1(82.86,1.6) v1(83.27,4.65) v1(83.93,30.53) v1(84.18,26.67) v1(84.54,2.9) v1(84.79,13.49) v1(84.79,11.35) v1(84.87,25.1) v1(84.87,22.56) v1(84.87,20.02) v1(84.87,17.48) v1(84.87,14.94) v1(84.87,12.4) v1(84.87,9.86) v1(84.87,7.32) v1(85.61,28.91) v1(85.99,4.47) v1(87.08,25.91) v1(87.08,23.37) v1(87.08,20.83) v1(87.08,18.29) v1(87.08,15.75) v1(87.08,13.21) v1(87.08,10.67) v1(87.08,8.13) v1(87.08,5.59) v1(88.5,28.04) v1(88.5,27.03) v1(89.52,28.04) v1(89.52,27.03) v1(90.53,28.04) v1(90.53,27.03) v1(95.36,30.78) v1(95.36,29.77) v1(96.63,30.78) v1(96.63,29.77) v1(97.77,30.78) v1(97.77,29.77) v1(100.54,6.85) v1(101.91,2) v1(103.76,26.13) v1(103.86,17.67) v1(105.72,2.05) v1(105.92,22.4) v1(106.1,14.25)
V3V3_REF_CDCI2: length 8.1
  TOP w0.254: FL9.3 80.02,10.67 C83.1 77.23,11.53 v1(76.48,11.53)
  TOP w0.305: C78.2 76.06,12.37 75.67,12.75 75.68,12.76 U12.3
  TOP w0.381: C78.2 v1(76.48,11.53)
  BOTTOM w0.381: C78.2 v1(76.48,11.53)
V3V3_VCO_CDCI2: length 2.2
  TOP w0.254: U12.24 73.6,14.8 73.45,14.66 ; C77.2 v1(72.37,13.39)
  TOP w0.356: C79.1 v1(72.5,11.99)
VDD12_CDCI2: length 12.1
  TOP w0.254: C60.1 v1(72.12,24.94)
  TOP w0.305: v1(75.36,19.74) 75.68,19.41 U12.16
  TOP w0.356: C69.2 v1(75.36,19.74)
  BOTTOM w0.356: v1(75.36,19.74) C69.2 73.2,20.55 72.12,21.63 v1(72.12,24.94) v1(71.1,24.94)
VDD34_CDCI2: length 11.2
  TOP w0.254: C61.1 73.39,25.49 v1(73.39,24.94)
  TOP w0.305: v1(76.5,19.74) 76.18,19.41 U12.15
  TOP w0.356: C70.2 v1(76.5,19.74)
  L04_SIG1 w0.356: v1(76.5,19.74) 75.94,20.29 75.94,23.41 v1(74.4,24.94) v1(73.39,24.94)
  BOTTOM w0.356: C70.2 v1(76.5,19.74)
2_BOARDID_A0: length 3.2
  TOP w0.356: R133.2 v1(50.53,13.66) U13.1
  BOTTOM w0.356: J18.8 50.46,13.59 v1(50.53,13.66)
2_BOARDID_A1: length 3.3
  TOP w0.356: U13.2 v1(49.26,13.66) R132.2
  BOTTOM w0.356: J18.9 49.66,13.26 v1(49.26,13.66)
2_BOARDID_A2: length 3.2
  TOP w0.356: U13.3 v1(47.99,13.66) R131.2
  BOTTOM w0.356: v1(47.99,13.66) 48.06,13.59 J18.11
2_BRD_DET: length 1.7
  BOTTOM w0.356: R282.1 44.86,4.94 J18.45
2_CLKGEN_REFCLK1N: length 14.7
  TOP w0.203: v1(68.36,16.48) 68.6,16.24 69.17,16.24 R125.1 69.73,16.24 70.24,16.24 R126.2 ; v1(67.18,11.05) 66.94,11.29 66.05,11.29 65.61,11.73 65.61,12.22 R142.2
  L04_SIG1 w0.102: v1(67.18,11.05) 67.36,11.23 67.88,11.23 69.11,12.46 69.86,12.46 70.61,13.21 70.61,15.54 69.96,16.19 68.65,16.19 v1(68.36,16.48)
2_CLKGEN_REFCLK1P: length 14.7
  TOP w0.203: R143.2 65.99,12.22 65.99,11.88 66.21,11.67 66.94,11.67 67.18,11.9 v1(67.18,11.91) ; R128.2 70.24,15.86 69.73,15.86 R129.1 69.17,15.86 68.6,15.86 v1(68.36,15.63)
  L04_SIG1 w0.102: v1(68.36,15.63) 68.68,15.95 69.86,15.95 70.37,15.44 70.37,13.31 69.76,12.7 69.01,12.7 67.79,11.48 66.72,11.48 66.62,11.58 66.62,11.81 66.72,11.91 v1(67.18,11.91)
2_CLKGEN_REFCLK2N: length 19.9
  TOP w0.203: v1(65.32,16.46) 65.61,16.18 65.61,15.6 R135.2 ; R112.2 73.52,22.25 73.52,22.63 R106.1 73.55,23.15 73.55,23.81 v1(73.75,24)
  L04_SIG1 w0.102: v1(73.75,24) 73.45,23.7 73.45,20.09 72.22,18.86 68.41,18.86 67.29,17.75 67.29,15.67 67.05,15.43 65.97,15.43 65.56,15.84 65.56,16.22 v1(65.32,16.46)
2_CLKGEN_REFCLK2P: length 19.9
  TOP w0.203: R136.2 65.99,15.6 65.99,16.18 v1(66.28,16.46) ; R111.2 73.13,22.25 73.13,22.63 R105.1 73.17,23.23 73.17,23.73 v1(72.9,24)
  L04_SIG1 w0.102: v1(72.9,24) 73.2,23.7 73.2,20.19 72.12,19.1 68.31,19.1 67.05,17.85 67.05,15.77 66.95,15.67 66.07,15.67 65.8,15.94 65.8,16.61 65.93,16.74 66.11,16.74 66.28,16.57 v1(66.28,16.46)
2_EEPROM_WP: length 1.6
  TOP w0.356: U13.7 R145.2
2_MCU_SCL: length 73
  TOP w0.356: R122.1 v1(82.15,18.08)
  L04_SIG1 w0.203: 59.01,27.99 J7.B5
  L04_SIG1 w0.234: 59.01,27.99 59.62,28.61 62.6,28.61 64.28,26.92 64.28,25.55 65.32,24.51 69.31,24.51 70.4,25.6 75.33,25.6 77.58,27.85 79.06,27.85 81.19,25.73 81.19,19.05 v1(82.15,18.08)
  BOTTOM w0.356: v1(82.15,18.08) 75.41,18.08 74.67,18.82 66.05,18.82 65.06,17.83 62,17.83 60.93,16.76 60.93,12.7 59.69,11.46 55.65,11.46 55.26,11.84 J18.2
2_MCU_SDA: length 39.8
  TOP w0.356: v1(54.85,13.77) 56.62,11.99 62.4,11.99 63.93,13.51 63.93,16.38 66.75,19.2 68.03,19.2 v1(68.69,19.86) 69.71,18.85 R121.1
  L04_SIG1 w0.203: J7.B6 58.01,23.94
  L04_SIG1 w0.234: 58.01,23.94 58.52,23.42 67.87,23.42 68.71,22.59 68.71,19.88 v1(68.69,19.86)
  BOTTOM w0.356: v1(54.85,13.77) 54.46,13.38 J18.3
2_PCIE_CLKREQN: length 2.9
  BOTTOM w0.356: J7.B12 50.01,29.59 R273.2
2_PCIE_PRSNT1N: length 32.4
  TOP w0.203: J7.A1 61.8,23.44 54.63,23.44 54.01,24.07 54.01,25.34 53.54,25.81 50.72,25.81 50.11,25.2 50.11,24.41 49.18,23.48 44.86,23.48 43.58,22.2
  TOP w0.356: R130.2 40.27,16.12 v1(40.27,16.12) 40.27,18.9 43.58,22.2
  BOTTOM w0.356: R276.2 v1(40.27,16.12)
2_PCIE_PRSNT2N: length 20.2
  TOP w0.356: J7.B17 43.72,24.73 43.07,25.37 40.71,25.37 38.7,23.36 38.7,15.04 39.26,14.48 v1(39.26,13.73)
  BOTTOM w0.356: J18.22 v1(39.26,13.73) R277.2 R276.1
2_PCIE_REFCLK_N: length 25.4
  TOP w0.203: R142.1 v1(64.57,13.38)
  L04_SIG1 w0.102: v1(64.57,13.38) 65.58,13.38 65.68,13.48 65.68,14.52 62.48,17.72 58.43,17.72 57.83,18.32 53,18.32 52.19,19.13 52.19,20.27 51.19,21.27 49.72,21.27 49.34,20.89 48.4,20.89 48.01,20.51 J7.A14
  BOTTOM w0.203: R142.1 v1(64.57,13.38)
2_PCIE_REFCLK_P: length 25.4
  TOP w0.203: R143.1 v1(67.03,13.38)
  L04_SIG1 w0.102: J7.A13 49.01,21.22 49.09,21.13 49.24,21.13 49.62,21.51 51.29,21.51 52.43,20.37 52.43,19.23 53.1,18.56 57.93,18.56 58.53,17.96 62.58,17.96 65.92,14.62 65.92,13.48 66.02,13.38 v1(67.03,13.38)
  BOTTOM w0.203: R143.1 v1(67.03,13.38)
2_PCIE_RESETN: length 54.1
  TOP w0.356: J7.A11 51.94,21.17 51.94,19.12 49.77,16.94 47.23,16.94 40.5,10.21 38.25,10.21 36.05,12.41 36.05,24.79 45.34,34.08 46.6,34.08 47.54,35.03 J6.2
2_PCIE_RST: length 4
  BOTTOM w0.356: J18.6 52.06,15.31 U26.1 52.17,15.42 R275.1
2_PCIE_RXN: length 40.5
  BOTTOM w0.224: J7.A17 44.55,21.78 arc(44.4,21.68) 44.23,21.64 38.35,21.64 arc(36.12,21.2) 34.22,19.93 29.66,15.37 arc(29.28,14.79) 29.14,14.12 29.14,6.09 arc(29.7,4.75) 31.04,4.19 38.27,4.19 arc(38.82,4.42) 39.05,4.97 39.05,5.51 arc(39.06,5.59) 39.11,5.66 39.2,5.75 arc(39.24,5.81) 39.26,5.89 J18.52
2_PCIE_RXP: length 40.5
  BOTTOM w0.224: J18.53 38.46,5.89 arc(38.47,5.81) 38.52,5.75 38.61,5.66 arc(38.65,5.59) 38.67,5.51 38.67,4.97 arc(38.55,4.69) 38.27,4.57 31.04,4.57 arc(29.97,5.02) 29.52,6.09 29.52,14.12 arc(29.63,14.65) 29.93,15.1 34.49,19.66 arc(36.26,20.84) 38.35,21.26 44.54,21.26 arc(44.54,21.26) 44.55,21.26 arc(44.71,21.23) 44.84,21.13 arc(45.01,20.89) 45.07,20.59 45.07,20.4 arc(45.2,20.08) 45.53,19.94 45.72,19.94 arc(45.92,20.02) J7.A16
2_PCIE_TCK: length 7.7
  TOP w0.203: 59.01,19.55 J7.A5
  TOP w0.356: TP9.1 58.89,16.59 58.89,18.79 59.01,18.92 59.01,19.55
2_PCIE_TDI: length 5.2
  TOP w0.203: J7.A6 58.01,19.55
  TOP w0.356: 58.01,19.55 58.01,15.56 TP8.1
2_PCIE_TDO: length 7.4
  TOP w0.203: 57.01,19.55 J7.A7
  TOP w0.356: TP7.1 57.15,16.33 57.15,18.31 57.01,18.45 57.01,19.55
2_PCIE_TMS: length 6.4
  TOP w0.203: 56.01,19.55 J7.A8
  TOP w0.356: TP6.1 54.86,15.29 56.44,16.87 56.44,18.01 56.01,18.45 56.01,19.55
2_PCIE_TRSTN: length 6.2
  TOP w0.203: 54.4,28.94 55.01,28.34 J7.B9
  TOP w0.356: 54.4,28.94 TP5.1
2_PCIE_TXN: length 59.2
  BOTTOM w0.224: J18.50 40.86,5.89 arc(40.87,5.81) 40.92,5.75 41.01,5.66 arc(41.05,5.59) 41.07,5.51 41.07,4.48 arc(40.53,3.18) 39.23,2.64 30.07,2.64 arc(28.19,3.42) 27.41,5.3 27.41,16.48 arc(27.65,17.68) 28.33,18.7 37.78,28.15 arc(38.82,28.84) 40.04,29.08 45.44,29.08 arc(46.39,28.76) 46.95,27.92 arc(46.98,27.75) 47,27.59 arc(47.01,27.51) 47.01,27.44 47.01,26.75 arc(47.09,26.35) 47.32,26 47.53,25.79 arc(47.69,25.42) 47.53,25.04 47.22,24.73 J7.B15
2_PCIE_TXP: length 59.2
  BOTTOM w0.224: J7.B14 47.61,27.13 arc(47.58,27.16) 47.56,27.19 arc(47.44,27.39) 47.38,27.62 arc(47.36,27.82) 47.32,28.01 arc(46.62,29.06) 45.44,29.46 40.04,29.46 arc(38.67,29.19) 37.51,28.42 28.07,18.97 arc(27.3,17.83) 27.03,16.48 27.03,5.3 arc(27.92,3.15) 30.07,2.26 39.23,2.26 arc(40.8,2.91) 41.45,4.48 41.45,5.51 arc(41.46,5.59) 41.51,5.66 41.6,5.75 arc(41.64,5.81) 41.66,5.89 J18.49
2_PCIE_WAKEN: length 41.2
  TOP w0.356: v1(29.21,22.07) 29.21,18.14 29.49,17.86 R309.2
  BOTTOM w0.356: v1(29.21,22.07) 29.21,22.99 38.86,32.64 49.47,32.64 50.74,31.37 50.74,30.01 51.15,29.6 R272.2 51.54,26.2 J7.B11
2_PCIE_WAKEN_3V3: length 23.6
  TOP w0.356: R309.1 29.49,14.12 30.2,13.41 31.59,13.41 32.3,12.7 32.3,7.09 33.12,6.27 42.66,6.27 v1(44.06,7.67)
  BOTTOM w0.356: J18.46 v1(44.06,7.67)
2_PORZ: length 51.4
  TOP w0.356: J6.1 44.95,36.96 39.91,36.96 33.63,30.67 33.63,12.5 36.65,9.47 42.34,9.47 44.73,11.86 44.73,12.93 v1(46.47,14.67)
  BOTTOM w0.356: v1(46.47,14.67) 46.48,14.67 47.26,13.89 J18.12
2_PORZ_OUT: length 82.8
  TOP w0.356: v1(51.29,16.31) 51.74,16.31 53.64,14.4 56.43,14.4 56.94,13.89 62.4,13.89 63.22,14.71 63.22,18.26 65.15,20.19 65.15,29.34 65.52,29.71 76.68,29.71 83.04,23.36 83.04,15.7 82.25,14.91 R134.1
  BOTTOM w0.356: J18.30 32.86,15.27 35.42,17.83 47.42,17.83 48.38,16.87 50.73,16.87 v1(51.29,16.31) 51.16,16.18 U26.2
2_REFCLK_IN1N: length 38.9
  L04_SIG1 w0.102: v1(65.36,10.74) 65.36,10.59 65.49,10.46 65.67,10.46 65.79,10.59 65.79,11.71 65.26,12.24 46.9,12.24 43.84,15.3 35.37,15.3 34.98,14.92 34.98,14.36 v1(35.29,14.05)
  BOTTOM w0.203: v1(65.36,10.74) 65.37,10.74 65.61,10.97 65.61,12.22 R281.2 ; v1(35.29,14.05) 35.05,13.82 35.05,13.26 35.26,13.05 J18.27
2_REFCLK_IN1P: length 38.9
  L04_SIG1 w0.102: v1(66.23,10.74) 66.04,10.93 66.04,11.81 65.36,12.48 47,12.48 43.94,15.54 35.27,15.54 34.74,15.02 34.74,14.36 v1(34.43,14.05)
  BOTTOM w0.203: v1(34.43,14.05) 34.67,13.82 34.67,13.27 34.46,13.06 J18.28 ; v1(66.23,10.74) 65.99,10.97 65.99,12.22 R280.2
2_REFCLK_OUT0N: length 64.7
  TOP w0.203: v1(78.96,26.42) 78.72,26.18 78.72,25.09 C65.1
  L04_SIG1 w0.102: v1(37.69,14.05) 37.36,14.38 37.36,14.55 37.47,14.66 43.33,14.66 46.55,11.43 63.17,11.43 64.97,9.63 78.08,9.63 79.4,10.95 79.4,14.33 78.65,15.07 78.65,26.11 v1(78.96,26.42)
  BOTTOM w0.203: v1(37.69,14.05) 37.45,13.82 37.45,13.26 37.66,13.05 J18.24
2_REFCLK_OUT0P: length 64.7
  TOP w0.203: v1(78.1,26.42) 78.34,26.18 78.34,25.09 C64.1
  L04_SIG1 w0.102: v1(78.1,26.42) 78.41,26.11 78.41,14.97 79.15,14.23 79.15,11.05 77.98,9.87 65.07,9.87 63.27,11.67 46.65,11.67 43.43,14.9 37.37,14.9 37.12,14.65 37.12,14.35 v1(36.83,14.05)
  BOTTOM w0.203: J18.25 36.86,13.05 37.07,13.26 37.07,13.82 v1(36.83,14.05)
2_REFCLK_OUT1N: length 43.1
  L04_SIG1 w0.102: v1(36.89,7.99) 36.58,8.3 36.58,10.02 33.89,12.71 33.89,15.27 36.36,17.73 45.32,17.73 47.7,15.35 58.17,15.35 58.57,15.75 62.61,15.75 62.75,15.6 62.75,15.42 62.65,15.32 v1(62.34,15.32)
  BOTTOM w0.203: C203.2 63.12,15.56 62.58,15.56 62.34,15.32 v1(62.34,15.32) ; J18.55 36.86,6.99 36.65,7.2 36.65,7.76 v1(36.89,7.99)
2_REFCLK_OUT1P: length 42.5
  L04_SIG1 w0.102: v1(62.34,16.18) 62.15,15.99 58.47,15.99 58.07,15.6 47.8,15.6 45.42,17.97 36.26,17.97 33.65,15.37 33.65,12.61 36.34,9.92 36.34,8.3 v1(36.03,7.99)
  BOTTOM w0.203: v1(62.34,16.18) 62.58,15.94 63.12,15.94 C201.2 ; J18.56 36.06,7 36.27,7.21 36.27,7.76 v1(36.03,7.99)
2_RESETN: length 44
  TOP w0.356: J6.3 50.08,35.73 43.3,28.94 41.47,28.94 37.66,25.13 37.66,14.87 38.55,13.98 38.55,13.44 38.96,13.02 41.13,13.02 45.87,17.76 v1(49.06,17.76)
  BOTTOM w0.356: U26.4 v1(49.06,17.76)
2_USB3_RXN: length 42.3
  BOTTOM w0.224: C232.1 83.87,11.91 arc(83.73,11.7) 83.68,11.46 83.68,9.97 arc(83.31,8.15) 82.28,6.61 81.49,5.82 arc(79.55,4.52) 77.26,4.06 49.55,4.06 arc(49.06,4.27) 48.86,4.75 J18.40
2_USB3_RXN_DB: length 35
  TOP w0.224: J4.9 73.54,37.88 73.54,35.48 73.57,35.46 73.57,35.15 U9.4 ; U9.7 73.61,33.32 arc(73.41,32.84) 72.93,32.64 72.63,32.64 arc(72.34,32.52) 72.22,32.23 72.22,31.87 arc(72.24,31.8) 72.28,31.73 v1(72.42,31.59)
  TOP w0.229: U9.4 U9.7
  BOTTOM w0.224: v1(72.42,31.59) 72.32,31.49 arc(72.28,31.43) 72.26,31.35 72.26,30.36 arc(72.41,30.01) 72.76,29.86 79.13,29.86 arc(79.69,29.75) 80.17,29.43 83.31,26.29 arc(83.59,25.87) 83.69,25.37 83.69,13.57 arc(83.76,13.22) C232.2
2_USB3_RXP: length 41.3
  BOTTOM w0.224: C233.1 83.1,11.93 arc(83.24,11.71) 83.29,11.46 83.29,9.97 arc(82.96,8.3) 82.01,6.88 81.22,6.08 arc(79.4,4.87) 77.26,4.45 49.55,4.45 arc(49.33,4.53) 49.24,4.75 49.24,5.49 arc(49.29,5.66) 49.43,5.75 arc(49.59,5.82) 49.66,5.98 J18.39
2_USB3_RXP_DB: length 35.9
  TOP w0.224: U9.6 73.11,34.11 arc(73.2,33.98) 73.23,33.82 73.23,33.32 arc(73.14,33.11) 72.93,33.02 72.63,33.02 arc(72.07,32.79) 71.84,32.23 71.84,31.83 71.85,31.83 arc(71.78,31.66) 71.61,31.59 v1(71.35,31.59) ; U9.5 73.16,35.16 73.16,36.78 arc(73.14,36.9) 73.07,36.99 72.89,37.18 arc(72.83,37.26) 72.81,37.36 J4.10
  TOP w0.229: U9.6 U9.5
  BOTTOM w0.224: v1(71.35,31.59) 71.42,31.66 71.66,31.66 arc(71.82,31.6) 71.88,31.44 71.88,30.36 arc(72.14,29.74) 72.76,29.48 79.13,29.48 arc(79.55,29.4) 79.9,29.16 83.04,26.02 arc(83.24,25.72) 83.31,25.37 83.31,13.62 arc(83.24,13.25) 83.03,12.93 C233.2
2_USB3_TXN: length 85.2
  TOP w0.224: v1(75.53,32.38) 75.35,32.56 arc(75.31,32.62) 75.29,32.7 75.29,33.4 arc(75.28,33.48) 75.23,33.54 75.22,33.56 arc(75.14,33.68) 75.11,33.82 U9.10 U9.1 75.11,36.14 arc(75.13,36.24) 75.18,36.32 arc(75.35,36.57) 75.41,36.87 J4.6
  BOTTOM w0.224: J18.43 46.46,3.39 arc(46.89,2.36) 47.92,1.93 80.68,1.93 arc(82.18,2.23) 83.45,3.08 84.86,4.49 arc(85.86,5.99) 86.22,7.75 86.22,25.78 arc(85.98,26.95) 85.32,27.95 81.95,31.31 arc(81.52,31.6) 81.01,31.7 75.65,31.7 arc(75.49,31.77) 75.43,31.93 75.43,32.12 arc(75.46,32.26) v1(75.53,32.38)
2_USB3_TXP: length 85.2
  TOP w0.224: v1(74.44,32.38) 74.71,32.38 arc(74.85,32.44) 74.91,32.58 74.91,33.33 arc(74.79,33.53) 74.73,33.76 arc(74.73,33.79) 74.73,33.82 arc(74.71,33.93) 74.64,34.03 74.61,34.06 U9.9 U9.2 74.61,35.46 74.73,35.58 74.73,36.14 arc(74.78,36.39) 74.91,36.59 arc(75,36.72) 75.03,36.87 75.03,36.95 74.76,37.22 J4.7
  BOTTOM w0.224: J18.42 47.26,5.98 arc(47.19,5.82) 47.03,5.75 arc(46.89,5.66) 46.84,5.49 46.84,3.39 arc(47.16,2.63) 47.92,2.31 80.68,2.31 arc(82.03,2.58) 83.18,3.35 84.59,4.76 arc(85.51,6.13) 85.83,7.75 85.83,25.78 arc(85.63,26.81) 85.05,27.68 81.68,31.05 arc(81.37,31.25) 81.01,31.32 75.65,31.32 arc(75.22,31.5) 75.05,31.93 75.05,32.16 arc(74.98,32.31) 74.82,32.38 v1(74.44,32.38)
2_USB_DM: length 65.5
  TOP w0.208: J4.2 81.46,37.35 81.32,37.21 81.32,36.76 v1(81.52,36.55) 81.38,36.41 U8.1
  L04_SIG1 w0.109: v1(81.52,36.55) 81.24,36.27 81.24,35.38 83.29,33.32 83.29,16.13 80.62,13.46 80.62,9.63 77.01,6.01 57.49,6.01 54.68,8.81 51.89,8.81 51.76,8.69 51.76,8.32 v1(52.09,7.99)
  BOTTOM w0.208: v1(52.09,7.99) 51.83,7.73 51.83,7.26 52.06,7.03 J18.36
2_USB_DP: length 65.5
  TOP w0.208: U8.2 80.88,36.42 v1(80.75,36.55) 80.98,36.78 80.98,37.22 80.81,37.39 J4.3
  L04_SIG1 w0.109: v1(80.75,36.55) 81.03,36.27 81.03,35.29 83.08,33.24 83.08,16.22 80.41,13.55 80.41,9.71 76.92,6.22 57.57,6.22 54.77,9.02 51.8,9.02 51.55,8.77 51.55,8.32 v1(51.23,7.99)
  BOTTOM w0.208: v1(51.23,7.99) 51.49,7.73 51.49,7.24 51.26,7 J18.37
2_USB_DRV_VBUS: length 62.8
  TOP w0.356: v1(92.87,25.72) R102.1 91.25,25.72 90.93,26.03 U10.4
  BOTTOM w0.356: J18.5 52.86,13.91 53.51,14.57 54.88,14.57 59.36,19.05 63.78,19.05 64.56,19.84 64.56,29.16 70.33,34.92 81.02,34.92 85.01,30.94 89.26,30.94 91.26,28.93 91.26,27.05 92.6,25.72 v1(92.87,25.72)
2_USB_ID: length 103.2
  TOP w0.305: v1(78.86,35.66) U8.3 80.38,35.73 80.16,35.95 J4.4
  TOP w0.356: v1(45.66,11.61) 45.66,9.09 44.78,8.2 44.78,7.21 43.96,6.4 43.96,3 44.88,2.08 81.54,2.08 84.06,4.6 84.06,25.32 78.25,31.13 78.25,35.05 v1(78.86,35.66)
  L04_SIG1 w0.234: J5.6 88.14,37.47 79.27,37.47 78.86,37.05 v1(78.86,35.66)
  BOTTOM w0.356: J18.14 v1(45.66,11.61)
2_USB_VBUS: length 75.6
  TOP w0.254: v1(82.35,35.16) 82.24,35.06 U8.6
  L04_SIG1 w0.381: v1(82.35,35.16) 83.74,35.16 86.39,32.5 86.39,26.75 86.17,26.52 86.17,9.47 81.39,4.7 44.11,4.7 v1(43.26,5.55)
  BOTTOM w0.381: J18.47 v1(43.26,5.55)
2_VCC_1V8: length 67
  L04_SIG1 w0.508: J19.3 22.84,12.5 24.56,14.22 27.15,14.22 42.27,29.34 45.68,29.34 46.31,28.7 47.76,28.7 49.34,30.28 67.93,30.28 v1(69.45,28.75) v1(70.47,28.75) 73.55,28.75 v1(74.34,27.97) v1(76.35,27.97)
  BOTTOM w0.508: C205.1 J19.3
2_VCC_3V3: length 45.8
  TOP w0.381: R109.2 v1(25.08,22.66) 31.31,22.66 32.74,21.23 v1(32.74,16.28) ; C66.1 v1(25.11,23.83) ; R103.1 v1(11.88,23.22)
  L04_SIG1 w0.381: v1(32.74,16.28) 35.07,18.62 50.59,18.62 53.06,16.15 54.86,16.15 55.13,16.42 v1(55.13,16.81) 54.72,17.22 v1(54.72,17.7)
  BOTTOM w0.381: v1(54.72,17.7) 54.59,17.7 54.51,17.78 C200.1 52.14,17.78 U26.5 ; R275.2 54.25,15.58 55.13,16.46 v1(55.13,16.81)
  vias: v1(22.42,32.94) v1(22.42,31.93) v1(23.43,32.94) v1(23.43,31.93)
2_VCC_5V: length 10.7
  TOP w0.254: C59.1 v1(93.84,21.31)
  TOP w0.381: R101.1 86.72,27.41 86.19,26.87 86.19,23.21 88.09,21.31 v1(90.03,21.31)
  vias: v1(18.4,6.34) v1(18.4,5.32) v1(18.4,4.31) v1(19.41,6.34) v1(19.41,5.32) v1(19.41,4.31) v1(90.03,20.04) v1(90.03,18.77) v1(91.3,21.31) v1(91.3,20.04) v1(91.3,18.77) v1(92.57,21.31) v1(92.57,20.04) v1(92.57,18.77) v1(93.84,20.04) v1(93.84,18.77)
2_VCC_12V: length 0.9
  TOP w0.203: 16.87,18.97 16.75,19.1 U11.4
  vias: v1(18.4,15.67) v1(18.4,14.66) v1(18.4,13.64) v1(19.41,15.67) v1(19.41,14.66) v1(19.41,13.64) v1(20.43,15.67) v1(20.43,14.66) v1(20.43,13.64)
2_VCC_FUN_3V3: length 31
  TOP w0.254: v1(69.71,18.21) 70.21,17.7 R123.1 ; R118.1 v1(69.71,19.86) ; R138.1 70.33,14.17 69.77,14.17 69.37,13.77 v1(68.82,13.77) ; R124.1 v1(82.15,17.07) ; R117.1 v1(82.15,20.12)
  TOP w0.508: v1(47.99,16.05) R131.1 R132.1 ; 55.16,4.11 55.42,4.37 55.42,10.85 50.93,15.33 R133.1 R132.1 ; R132.1 v1(49.26,16.05)
  BOTTOM w0.508: C202.1 43.54,14.72 44.88,16.05 v1(47.99,16.05) v1(49.26,16.05)
  vias: v1(68.58,8.78) v1(68.58,7.8) v1(79.56,7.74) v1(80.7,7.74)
2_VCC_PCIE_3V3: length 7.7
  TOP w0.356: R99.2 v1(27.53,34.8)
  TOP w0.508: C55.1 55.99,26.75 J7.B8 ; C71.1 54.01,20.23 J7.A10
  BOTTOM w0.356: R277.1 v1(39.26,16.1)
  BOTTOM w0.381: R273.1 v1(50.02,31.17) ; R272.1 v1(51.54,31.17)
  vias: v1(27.53,37.34) v1(27.53,36.07) v1(27.53,33.53) v1(28.8,37.34) v1(28.8,36.07) v1(28.8,34.8) v1(28.8,33.53) v1(30.07,37.34) v1(30.07,36.07) v1(30.07,34.8) v1(30.07,33.53)
2_VCC_PCIE_12V: length 11.4
  TOP w0.508: C72.1 61.47,19.69 J7.A2 ; C72.1 v1(62.34,18.47) ; C72.1 C74.1 v1(62.34,17.2) ; C56.1 v1(62.53,29.64) ; C56.1 C53.1 v1(62.53,30.91) ; C56.1 61.53,27.21 J7.B2
  vias: v1(24.66,20.43) v1(24.66,17.82) v1(24.66,16.8) v1(25.68,20.41) v1(25.7,19.1) v1(25.68,17.82) v1(25.68,16.8) v1(26.69,20.41) v1(66.22,26.87) v1(66.22,25.95) v1(67.24,26.87) v1(67.24,25.95)
2_WKUP_SCL: length 9.8
  TOP w0.356: U13.6 47.99,8.43 48.5,8.94 53.51,8.94 54.46,8 v1(54.46,7.92)
  BOTTOM w0.356: J18.33 v1(54.46,7.92)
2_WKUP_SDA: length 12.1
  TOP w0.356: v1(53.66,9.7) 53.61,9.65 47.62,9.65 46.72,8.75 U13.5
  BOTTOM w0.356: v1(53.66,9.7) J18.34
CDCI2_EEPROMSEL: length 3.7
  TOP w0.305: R138.2 v1(72.25,14.4) 73.15,15.3 U12.23
  BOTTOM w0.356: R138.2 v1(72.25,14.4)
CDCI2_OE1: length 3.7
  TOP w0.305: v1(72.25,17.7) 73.15,16.8 U12.20
  TOP w0.356: R123.2 v1(72.25,17.7)
  BOTTOM w0.356: R123.2 v1(72.25,17.7)
CDCI2_OE2: length 5.2
  TOP w0.305: U12.19 73.66,17.3 72.12,18.85 R121.2
  TOP w0.356: R116.1 R118.2 R121.2
CDCI2_OE3: length 4.8
  TOP w0.305: U12.12 78.32,17.3 79.1,18.08 R122.2
  TOP w0.356: R122.2 R120.1 R117.2
CDCI2_OE4: length 3.6
  TOP w0.305: R127.1 R124.2 80.2,16.8 U12.11
CDCI2_REFSEL: length 1.8
  TOP w0.305: v1(76.37,13.13) 76.18,13.33 U12.4
  BOTTOM w0.356: v1(76.37,13.13) 76.27,13.23 R279.1
CDCI2_RST: length 3.7
  TOP w0.305: U12.8 79.35,15.3 79.74,14.91 R134.2 R141.1
CDCI2_XIN: length 9.1
  TOP w0.305: U12.1 74.68,11.9 R144.1 74.51,10.6 C80.2
  TOP w0.356: C80.2 74.5,10.29 74.11,9.91 72.94,9.91 72.59,9.55 72.59,8.08 73.54,7.12 Y4.3
CDCI2_XOUT: length 5.6
  TOP w0.305: C81.2 75.35,10.6 R144.2 75.18,11.9 U12.2
  TOP w0.356: Y4.1 76.03,9.72 75.36,10.39 C81.2
CDCI2_Y0: length 3.3
  TOP w0.305: TP10.1 79.61,13.51 78.32,14.8 U12.7
CDCI2_Y1N: length 2.6
  TOP w0.203: U12.21 73.13,16.3 73.07,16.24 72.2,16.24 71.88,16.56 R126.1
CDCI2_Y1P: length 2.6
  TOP w0.203: U12.22 73.13,15.8 73.07,15.86 72.2,15.86 71.88,15.54 R128.1
CDCI2_Y2N: length 4.2
  TOP w0.203: R112.1 73.83,20.61 73.52,20.29 73.52,19.89 73.85,19.56 74.57,19.56 75.12,19 75.12,18.64 75.18,18.58 U12.17
CDCI2_Y2P: length 4.2
  TOP w0.203: U12.18 74.68,18.61 74.74,18.67 74.74,18.85 74.41,19.18 73.69,19.18 73.13,19.74 73.13,20.29 72.82,20.61 R111.1
CDCI2_Y3N: length 4.2
  TOP w0.203: R114.1 79.04,20.61 78.72,20.29 78.72,19.74 78.16,19.18 77.45,19.18 77.12,18.85 77.12,18.67 77.18,18.61 U12.13
CDCI2_Y3P: length 4.2
  TOP w0.203: U12.14 76.68,18.58 76.74,18.64 76.74,19 77.29,19.56 78.01,19.56 78.34,19.89 78.34,20.29 78.02,20.61 R113.1
FAULTN: length 1.8
  TOP w0.356: R101.2 86.79,29.03 U10.8
PWR_GOOD2: length 1.7
  TOP w0.279: R103.2 14.55,22.33 U11.14
USB_SHIELD2:
  vias: v1(66.48,40.2) v1(67.75,40.2) v1(68.89,39.06) v1(70.13,40.84) v1(70.13,39.82) v1(72.88,40.26) v1(73.64,40.26) v1(83.48,40.84) v1(83.48,39.7) v1(86.14,39.7) v1(86.16,40.84)
N16935843: length 2.4
  TOP w0.203: R114.2 78.72,22.25 78.72,22.63 R108.1 78.76,23.15 78.76,23.62 78.99,23.85 C65.2
N16935846: length 2.4
  TOP w0.203: C64.2 78.38,23.49 78.38,23.23 R107.1 78.34,22.63 78.34,22.25 R113.2
N17014016: length 7.7
  TOP w0.279: U11.7 22.88,20.83 R110.1 R109.1
  TOP w0.356: R109.1 23.51,22.71 C66.2
N17014112: length 2.8
  TOP w0.254: U11.11 16.75,24.27 16.44,24.57
  TOP w0.279: 16.44,24.57 16.25,24.38 U11.12
N17014164: length 1.1
  TOP w0.356: C68.1 21.23,21.68 R104.2
N17014176: length 1.3
  TOP w0.279: U11.1 R115.1
N17014182: length 2.1
  TOP w0.279: U11.9 17.75,23.99 18.19,24.43 C62.1
N17014200: length 1.5
  TOP w0.279: C63.2 15.75,23.58 U11.13
N17027241: length 1.6
  TOP w0.356: U10.5 90.68,29.22 R100.1
N17070998: length 4.8
  TOP w0.203: R136.1 v1(67.07,14.44)
  BOTTOM w0.203: v1(67.07,14.44) 66.21,14.44 66.01,14.65 66.01,15.54 65.6,15.94 64.67,15.94 C201.1
N17071009: length 4.1
  TOP w0.203: R135.1 v1(64.57,14.44)
  BOTTOM w0.203: C203.1 64.67,15.56 65.44,15.56 65.63,15.38 65.63,14.65 65.42,14.44 v1(64.57,14.44)

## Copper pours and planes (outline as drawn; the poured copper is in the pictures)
DGND2 on TOP: 74.47,26.54 74.47,27.15 76.37,27.15 76.83,27.61 77.16,27.61 77.24,27.53 77.24,26.21 77.11,26.09 76.86,26.09 76.4,26.54
DGND2 on TOP: 17.85,21.21 17.83,21.23 14.45,21.23 14.27,21.41 13.43,21.41 13.43,21.92 17.83,21.92 17.85,21.95 19.78,21.95 19.78,22.91 20.52,22.91 20.52,21.21
DGND2 on TOP: 10.02,41.07 86.66,41.07 86.66,38.53 87.63,37.57 91.21,37.57 92.3,38.66 92.3,41.07 107.49,41.07 107.49,0.79 10.02,0.79 ; 9 cut-outs
DGND2 on TOP: 70.04,9.26 70.65,9.26 70.65,7.35 71.1,6.9 71.1,6.57 71.03,6.49 69.71,6.49 69.58,6.62 69.58,6.87 70.04,7.33
DGND2 on TOP: 79.29,9.14 79.29,9.75 81.2,9.75 81.66,10.21 81.99,10.21 82.06,10.13 82.06,8.81 81.94,8.69 81.68,8.69 81.22,9.14
DGND2 on TOP: 70.91,26.54 70.91,27.15 69.01,27.15 68.55,27.61 68.22,27.61 68.14,27.53 68.14,26.21 68.27,26.09 68.52,26.09 68.98,26.54
DGND2 on BOTTOM: 9.51,41.58 108,41.58 108,0.51 9.51,0.51 ; 2 cut-outs
DGND2 on BOTTOM: 65.39,22.66 65.39,20.12 67.93,20.12 67.93,22.66
DGND2 on L02_GND1: 9.54,0.51 9.54,41.56 65.23,41.56 65.23,38.51 66.41,37.33 71.09,37.33 72.97,39.21 82.05,39.21 82.63,38.63 86.59,38.63 87.35,39.39 87.35,41.56 107.99,41.56 107.99,0.51
DGND2 on L03_PWR: 58.98,40.94 64.24,40.94 65.26,39.93 65.26,38.5 66.42,37.33 71.15,37.33 73.03,39.21 82,39.21 82.55,38.66 86.62,38.66 87.35,39.39 87.35,40.94 107.42,40.94 107.42,1.14 98.1,1.14 98.1,22.56 85.75,22.56 85.75,21.81 69.27,21.81 69.27,32.61 58.98,32.61
DGND2 on L04_SIG1: 107.32,40.97 107.32,1.14 98.3,1.14 98.25,1.19 98.25,22.53 86.24,22.53 86.24,6.42 84.72,4.9 30.68,4.9 25.73,9.85 10.04,9.85 10.04,41.07 62.36,41.07 66.22,37.21 71.05,37.21 73.05,39.21 81.82,39.21 82.4,38.63 86.74,38.63 87.48,39.37 87.48,40.97 ; 2 cut-outs
DGND2 on L05_GND2: 9.54,0.51 9.54,41.56 66.01,41.56 66.01,38.25 66.04,38.23 67.94,38.23 68.73,39.01 72.77,39.01 73.43,39.67 82.67,39.67 83.28,39.07 86.79,39.07 86.84,39.12 86.84,41.56 107.99,41.56 107.99,0.51
V3V3_VCO_CDCI2 on TOP: 71.1,7.92 71.1,9.83 71.23,9.96 71.23,11.23 71.36,11.35 71.36,12.75 71.1,13 71.1,13.77 72.88,13.77 73.13,14.02 73.13,14.78 73.26,14.91 74.15,14.91 74.15,13.26 71.99,11.1 71.99,7.92
V3V3_VCO_CDCI2 on BOTTOM: 71.23,13.64 71.23,11.73 72.88,11.73 72.88,13.64
VDD12_CDCI2 on TOP: 69.45,26.09 71.1,26.09 71.36,25.83 72.37,25.83 72.5,25.7 72.5,24.69 69.45,24.69
VDD34_CDCI2 on TOP: 73.01,25.83 73.01,24.69 75.93,24.69 75.93,26.09 74.15,26.09 73.9,25.83
(no net) on TOP: 15.6,24.65 16.2,24.05 16.2,22.91 16.81,22.91 16.81,24.04 17.1,24.33 17.1,31.67 12.19,31.67 12.19,25.17 15.39,25.17 15.6,24.96
(no net) on TOP: 24.77,26.18 24.77,36.4 20.23,36.4 17.89,34.06 17.89,26.56 18.27,26.18
(no net) on TOP: 16.62,19.05 16.62,16.3 16.44,16.12 16.44,9.58 20.94,9.58 20.94,12.5 22.45,14.01 22.45,15.58 22.94,16.07 22.94,20.06 22.78,20.22 20.94,20.22 20.94,20.24 16.7,20.24 16.7,19.13
2_USB_VBUS on TOP: 91.44,34.42 89.08,36.78 89.08,37.82 88.27,38.63 82.02,38.63 82.02,35.1 82.28,34.85 83.62,34.85 87.58,30.89 87.6,30.89 88.98,29.51 88.98,28.7 89.18,28.5 89.97,28.5 90.12,28.65 90.12,31.09 91.44,32.41
